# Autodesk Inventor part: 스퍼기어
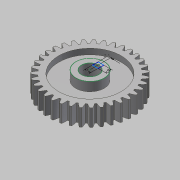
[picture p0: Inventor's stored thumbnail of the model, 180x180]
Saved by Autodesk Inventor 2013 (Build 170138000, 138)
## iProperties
Created: 2013-08
Part Number: 스퍼기어
Material: 강
Document SubType Name: Modeling
Designer: 한국산업디자인학원
Categories: <?xml version="1.0" encoding="UTF-16"?> <MemberInstance><Categories><FamilyTemplate><FamilyTemplateParameter ValueType="xs:double" Id="1" ObjectReferenceKey="da
Density: 1 g/cm^3
CustomPartVersion: 1
Author: 한국산업디자인학원
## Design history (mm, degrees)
sketch "Sketch1"
  geometry: C1 r 37 at (0, 0)
  constraints: 1 centre point
  dimensions: "d0" = 74 diameter of C1 (= da_da)
extrude "Extrusion1" new body sketch "Sketch1" distance "d1" = 15 (= da_b); taper "d2" = 0 deg
workplane "Work Plane2"
feature "피치 지름" dims "d4" = 10, "d5" = 0
workplane "Work Plane8"
workplane "Work Plane9"
feature "스퍼 기어" dims "da_b" = 15, "da_d" = 70, "da_aw" = 70, "da_da" = 74, "da_df" = 65, "da_dw" = 70, angle "da_beta" = 0 deg, "da_lefttooth" = 0, "da_righttooth" = 0
node "작업 평면11"
sketch "스케치3"
  geometry: C1 r 12.5 at (0, 0); 1 further point
  constraints: 1 centre point, 1 coincident
  dimensions: "d50" = 25 diameter of C1
extrude "돌출2" join sketch "스케치3" distance "d51" = 31; taper "d52" = 0 deg
hole "구멍1" diameter "d55" = 15; stored, may be unused: countersink angle "d59" = 90 deg, drill point angle "d61" = 0 deg; dims "d53" = 10, "d54" = 10, "d56" = 6, "d57" = 4, "d58" = 2, "d60" = 8
sketch "스케치4"
  geometry: L1 (0, 28.305)-(0, -28.305); L2 (35, 15)-(35, 0) reference; L3 (35, 0)-(12.5, 0) reference; L4 (12.5, 0)-(12.5, -13) reference; L5 (12.5, -13)-(7.5, -13) reference; L6 (7.5, -13)-(7.5, 18) reference; L7 (7.5, 18)-(12.5, 18) reference; L8 (12.5, 18)-(12.5, 15) reference; L9 (12.5, 15)-(35, 15) reference; L10 (-35, 0)-(-35, 15) reference; L11 (-35, 15)-(-12.5, 15) reference; L12 (-12.5, 15)-(-12.5, 18) reference; L13 (-12.5, 18)-(-7.5, 18) reference; L14 (-7.5, 18)-(-7.5, -13) reference; L15 (-7.5, -13)-(-12.5, -13) reference; L16 (-12.5, -13)-(-12.5, 0) reference; L17 (-12.5, 0)-(-35, 0) reference; L18 (27.5, 15)-(12.5, 15); L19 (12.5, 15)-(12.5, 10); L20 (12.5, 10)-(27.5, 10); L21 (27.5, 10)-(27.5, 15); L22 (27.5, 0)-(12.5, 0); L23 (12.5, 0)-(12.5, 5); L24 (12.5, 5)-(27.5, 5); L25 (27.5, 5)-(27.5, 0); 2 further points
  constraints: 18 end point, 4 parallel, 2 collinear, 2 horizontal, 2 perpendicular, 2 point on line, 1 coincident, 1 midpoint, 1 vertical
  dimensions: "d62" = 5 distance of L20.end L18.start; "d64" = 5 distance of L24.end L22.start; "d65" = 55 diameter of L21 L1; "d66" = 25 diameter of L19 L1
revolve "회전1" sketch "스케치4" stored, may be unused: angle "d67" = 90 deg
sketch "스케치5"
  geometry: L1 (-2.5, 9.624)-(2.5, 9.624); L2 (2.5, 9.624)-(2.5, 4.624); L3 (2.5, 4.624)-(-2.5, 4.624); L4 (-2.5, 4.624)-(-2.5, 9.624); C1 r 7.5 at (0, 0) reference; C2 r 12.5 at (0, 0) reference
  constraints: 8 end point, 2 parallel, 1 horizontal, 1 perpendicular
  dimensions: "d68" = 5 distance of L2.end L3.end; "d69" = 5 distance of L1.end L2.end; "d70" = 2.5 distance from line of C1.centre L4
body "Solid1"
sketch "Sketch2"
  geometry: C1 r 37 at (0, 0) reference; C2 r 35 at (0, 0)
  constraints: 1 centre point, 1 coincident
  dimensions: "d3" = 70 diameter of C2 (= da_dw)
body "Srf1"
node "절단 모서리 투영1"
other parameters: "d17" = 0, "d34" = 0.8976 (computed from da_z), "d39" = 0, "d41" = 0, "d47" = 0, "d48" = 0, "d49" = 3
